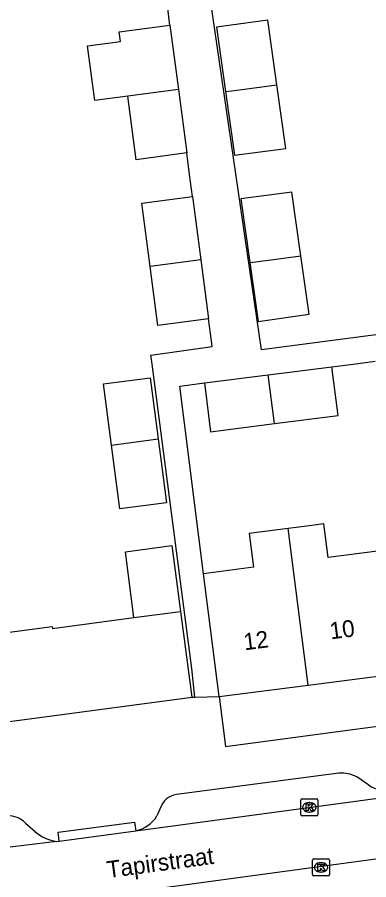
# Model space of a CAD drawing. Extents: x 163150 to 163546, y 380933 to 381635.
# Drawn here: x 163463.2 to 163484.1, y 381091.7 to 381142.9 of the extents above; entities that cross this region are included whole.
import ezdxf

# ---------------------------------------------------------------- set-up
doc = ezdxf.new("R2010")
doc.units = 0
for name, color, linetype in [('IMGEO_Kolk', 7, 'Continuous'), ('IMGEO_Openbare_ruimte_label', 7, 'Continuous'), ('IMGEO_Pand', 7, 'Continuous'), ('IMGEO_Pand_nummerreeks', 7, 'Continuous'), ('IMGEO_Rijbaan_lokaal_open', 7, 'Continuous'), ('IMGEO_Voetpad_open', 7, 'Continuous')]:
    doc.layers.add(name, color=color, linetype=linetype)

msp = doc.modelspace()

# ---------------------------------------------------------------- linework, layer by layer
at = {"layer": 'IMGEO_Kolk'}
for p, q in [((163480.024, 381095.54), (163480.024, 381096.392)), ((163480.099, 381096.466), (163480.951, 381096.466)), ((163481.025, 381096.392), (163481.025, 381095.54)), ((163480.512, 381096.246), (163480.537, 381096.246)), ((163480.951, 381095.466), (163480.099, 381095.466)), ((163480.535, 381095.686), (163480.51, 381095.686)), ((163480.721, 381091.973), (163480.721, 381092.825)), ((163480.796, 381092.899), (163481.648, 381092.899)), ((163481.722, 381092.825), (163481.722, 381091.973)), ((163481.209, 381092.679), (163481.234, 381092.679)), ((163481.648, 381091.899), (163480.796, 381091.899)), ((163481.232, 381092.119), (163481.207, 381092.119))]:
    msp.add_line(p, q, dxfattribs=at)
for points in [[(163480.024, 381095.54), (163480.024, 381096.392)], [(163480.099, 381096.466), (163480.951, 381096.466)], [(163481.025, 381096.392), (163481.025, 381095.54)], [(163480.345, 381096.166), (163480.468, 381096.166), (163480.468, 381096.015), (163480.598, 381096.166), (163480.762, 381096.166), (163480.616, 381096.015), (163480.769, 381095.766), (163480.617, 381095.766), (163480.532, 381095.93), (163480.468, 381095.863), (163480.468, 381095.766), (163480.345, 381095.766), (163480.345, 381096.166)], [(163480.951, 381095.466), (163480.099, 381095.466)], [(163480.721, 381091.973), (163480.721, 381092.825)], [(163480.796, 381092.899), (163481.648, 381092.899)], [(163481.722, 381092.825), (163481.722, 381091.973)], [(163481.042, 381092.599), (163481.165, 381092.599), (163481.165, 381092.448), (163481.295, 381092.599), (163481.459, 381092.599), (163481.313, 381092.448), (163481.466, 381092.199), (163481.314, 381092.199), (163481.229, 381092.363), (163481.165, 381092.296), (163481.165, 381092.199), (163481.042, 381092.199), (163481.042, 381092.599)], [(163481.648, 381091.899), (163480.796, 381091.899)]]:
    msp.add_lwpolyline(points, dxfattribs=at)
for centre, start, end in [((163480.101, 381096.39), 91.552, 178.448), ((163480.101, 381096.39), 91.552, 178.448), ((163480.949, 381096.39), 1.552, 88.448), ((163480.949, 381096.39), 1.552, 88.448), ((163480.101, 381095.542), 181.552, 268.448), ((163480.101, 381095.542), 181.552, 268.448), ((163480.949, 381095.542), 271.552, 358.448), ((163480.949, 381095.542), 271.552, 358.448), ((163480.798, 381092.823), 91.552, 178.448), ((163480.798, 381092.823), 91.552, 178.448), ((163481.646, 381092.823), 1.552, 88.448), ((163481.646, 381092.823), 1.552, 88.448), ((163480.798, 381091.975), 181.552, 268.448), ((163480.798, 381091.975), 181.552, 268.448), ((163481.646, 381091.975), 271.552, 358.448), ((163481.646, 381091.975), 271.552, 358.448)]:
    msp.add_arc(centre, 0.0765, start, end, dxfattribs=at)
for centre, major_axis, ratio, start_param, end_param in [((163480.511, 381095.966), (-0.387, 0.002), 0.722429, 4.712389, 7.853982), ((163480.536, 381095.966), (-0.39, 0.002), 0.717154, 1.570796, 4.712389), ((163481.208, 381092.399), (-0.387, 0.002), 0.722429, 4.712389, 7.853982), ((163481.233, 381092.399), (-0.39, 0.002), 0.717154, 1.570796, 4.712389)]:
    msp.add_ellipse(centre, major_axis=major_axis, ratio=ratio, start_param=start_param, end_param=end_param, dxfattribs=at)
at = {"layer": 'IMGEO_Pand'}
for points in [[(163469.745, 381138.178), (163467.791, 381137.918), (163467.358, 381141.161), (163469.318, 381141.422), (163469.242, 381141.999), (163472.251, 381142.395)], [(163472.251, 381142.395), (163472.753, 381138.579)], [(163478.595, 381138.854), (163478.054, 381142.681), (163475.016, 381142.281), (163475.557, 381138.453)], [(163475.557, 381138.453), (163475.92, 381138.501), (163476.077, 381138.522), (163478.595, 381138.854)], [(163475.557, 381138.453), (163476.093, 381134.667), (163479.13, 381135.067), (163478.595, 381138.854)], [(163472.753, 381138.579), (163469.745, 381138.178)], [(163472.753, 381138.579), (163473.25, 381134.806)], [(163473.25, 381134.806), (163470.242, 381134.405), (163469.745, 381138.178)], [(163471.076, 381128.062), (163470.582, 381131.822), (163473.589, 381132.223)], [(163473.589, 381132.223), (163474.084, 381128.463)], [(163480.029, 381128.698), (163479.494, 381132.483), (163476.458, 381132.083), (163476.992, 381128.297)], [(163476.992, 381128.297), (163477.355, 381128.345), (163477.49, 381128.363), (163477.763, 381128.399), (163478.111, 381128.445), (163480.029, 381128.698)], [(163476.992, 381128.297), (163477.486, 381124.805), (163480.518, 381125.233), (163480.029, 381128.698)], [(163474.084, 381128.463), (163471.076, 381128.062)], [(163474.544, 381124.968), (163471.535, 381124.572), (163471.076, 381128.062)], [(163474.084, 381128.463), (163474.544, 381124.968)], [(163478.079, 381121.635), (163481.868, 381122.117)], [(163478.454, 381118.743), (163482.244, 381119.225), (163481.868, 381122.117)], [(163468.778, 381117.462), (163468.302, 381121.103), (163471.069, 381121.464), (163471.544, 381117.83)], [(163474.3, 381121.155), (163478.079, 381121.635)], [(163478.454, 381118.743), (163478.079, 381121.635)], [(163474.3, 381121.155), (163474.668, 381118.262), (163478.454, 381118.743)], [(163471.544, 381117.83), (163472.038, 381114.045), (163469.272, 381113.677), (163468.778, 381117.462)], [(163468.778, 381117.462), (163471.544, 381117.83)], [(163484.568, 381111.17), (163481.65, 381110.799), (163481.398, 381112.79), (163480.377, 381112.661), (163479.261, 381112.519)], [(163479.261, 381112.519), (163477.723, 381112.324), (163476.964, 381112.228), (163477.22, 381110.211), (163474.249, 381109.834)], [(163480.467, 381103.224), (163479.261, 381112.519)], [(163470.116, 381107.225), (163469.605, 381111.132), (163472.371, 381111.5), (163472.882, 381107.595)], [(163475.175, 381102.551), (163474.544, 381107.512), (163474.249, 381109.834)], [(163470.116, 381107.225), (163472.882, 381107.595)], [(163472.882, 381107.595), (163473.559, 381102.505)], [(163460.755, 381106.1), (163465.255, 381106.699), (163465.271, 381106.578), (163470.116, 381107.225)], [(163480.467, 381103.224), (163485.516, 381103.866)], [(163475.175, 381102.551), (163480.467, 381103.224)], [(163451.716, 381099.596), (163473.559, 381102.505)]]:
    msp.add_lwpolyline(points, dxfattribs=at)
at = {"layer": 'IMGEO_Rijbaan_lokaal_open'}
for points in [[(163470.232, 381094.562), (163500, 381098.587), (163500.533, 381098.659), (163506.154, 381099.43)], [(163507.201, 381095.911), (163500, 381094.955), (163488.993, 381093.493), (163470.891, 381091.039)], [(163465.682, 381093.963), (163470.232, 381094.562)], [(163465.527, 381093.942), (163453.767, 381092.507)], [(163465.527, 381093.942), (163465.682, 381093.963)]]:
    msp.add_lwpolyline(points, dxfattribs=at)
at = {"layer": 'IMGEO_Voetpad_open'}
for points in [[(163495.959, 381125.509), (163477.678, 381123.119), (163473.262, 381153.534), (163473.423, 381153.559)], [(163472.251, 381142.395), (163472.076, 381143.722), (163471.908, 381144.999)], [(163473.589, 381132.223), (163473.419, 381133.519), (163473.25, 381134.806)], [(163473.737, 381102.51), (163473.559, 381104.203), (163471.196, 381122.272), (163471.123, 381122.795), (163474.766, 381123.309), (163474.716, 381123.663), (163474.544, 381124.968)], [(163481.868, 381122.117), (163483.126, 381122.277), (163484.433, 381122.444)], [(163474.249, 381109.834), (163472.833, 381120.968), (163473.006, 381120.99), (163474.3, 381121.155)], [(163475.175, 381102.551), (163475.554, 381099.568), (163494.208, 381102.063), (163500, 381102.823), (163509.388, 381104.055)], [(163473.559, 381102.505), (163473.737, 381102.51)], [(163473.737, 381102.51), (163475.175, 381102.551)], [(163482.276, 381097.996), (163472.797, 381096.739)], [(163484.056, 381097.284), (163483.34, 381097.777)], [(163471.746, 381096.069), (163471.482, 381095.451)], [(163463.666, 381095.033), (163464.238, 381094.53)], [(163465.682, 381093.963), (163465.605, 381094.484), (163470.149, 381095.093), (163470.232, 381094.562)]]:
    msp.add_lwpolyline(points, dxfattribs=at)
for centre, radius, start, end in [((163482.39, 381095.854), 2.145, 63.6996, 93.0393), ((163485.298, 381099.164), 2.254, 236.5453, 315.4769), ((163472.803, 381095.57), 1.169, 90.2885, 154.7456), ((163462.643, 381094.032), 1.432, 44.3794, 91.1946), ((163469.719, 381096.607), 2.108, 284.0895, 326.7514), ((163465.82, 381096.291), 2.368, 228.0696, 262.8885)]:
    msp.add_arc(centre, radius, start, end, dxfattribs=at)

# ---------------------------------------------------------------- texts
at = {"layer": 'IMGEO_Openbare_ruimte_label'}
msp.add_text('Tapirstraat', height=1, rotation=7.7007, dxfattribs=at).set_placement((163468.569, 381091.761))
at = {"layer": 'IMGEO_Pand_nummerreeks'}
for s, p in [('10', (163481.799, 381105.933)), ('12', (163476.681, 381105.283))]:
    msp.add_text(s, height=1, rotation=7.2422, dxfattribs=at).set_placement(p)

doc.saveas('drawing.dxf')
